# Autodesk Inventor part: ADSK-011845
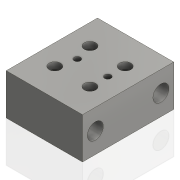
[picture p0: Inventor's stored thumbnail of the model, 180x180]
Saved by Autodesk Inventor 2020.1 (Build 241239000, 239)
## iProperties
Created: 1999-11
Part Number: ADSK-011845
Material: Aluminum
Document SubType Name: Modeling
Designer: sspink
Density: 2.71 g/cm^3
Appearance: Steel
Mass: 161.914 g
Surface Area: 152.118 cm^2
Volume: 59.747 cm^3
Control State: 0
Master: False
Checked Out: False
Shininess: 0.0
Length Units: 11269
Angle Units: 11279
Time Units: 11290
Mass Units: 11283
Length Display Precision: 3
Angle Display Precision: 2
Compacted: True
Dimensions: 47,6x25,6x57 mm
Mass: 0,162 kg
DocNumber: ADSK-011845.ipt
Folder: 01 - Themengebiete\Simplification\01 - Packaging machine\
VDS_Category: 3D Komponenten
Density: 0.0
Volumn: 0.0
Area: 0.0
PropertySet Name: Model Information
Author: sspink
Revision Number: -
Title: Zylinder - Body
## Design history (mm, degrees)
node "Solide1"
  node "Extrusion1" dims "d2" = 56.9976, "d3" = 0
  node "Hole2" dims "d26" = 3.683, "d27" = 9.525, "d28" = 6.35, "d29" = 60 deg, "d30" = 19.05, "d31" = 118 deg
  node "Hole3" dims "d32" = 4.318, "d33" = 7.1374, "d34" = 4.318, "d35" = 60 deg, "d36" = 12.7, "d37" = 118 deg
  node "Extrusion2" dims "d61" = 57.15, "d62" = 0
  node "Hole7" dims "d75" = 3.9624, "d76" = 9.525, "d77" = 6.35, "d78" = 60 deg, "d79" = 12.7, "d80" = 118 deg
sketch "Sketch3"
  geometry: L1 (0, 0)-(0, 56.998) reference; L2 (12.812, 17.499)-(34.812, 17.499); L3 (34.812, 17.499)-(34.812, 39.499); L4 (34.812, 39.499)-(12.812, 39.499); L5 (12.812, 39.499)-(12.812, 17.499); L6 (0, 0)-(47.625, 0) reference; 6 further points
  constraints: 8 end point, 4 midpoint, 2 coincident, 2 parallel, 1 horizontal, 1 horizontal alignment, 1 perpendicular, 1 vertical alignment
  dimensions: "d81" = 22 distance of L4.end L2.start; "d82" = 22 distance of L3.end L4.end
node "Corps solides"
node "Corps surfaciques"
sketch "Sketch1"
  geometry: L1 (-19.199, -4.517)-(28.426, -4.517) reference; L2 (28.426, -4.517)-(28.426, 21.086) reference; L3 (28.426, 21.086)-(-19.199, 21.086); L4 (-19.199, 21.086)-(-19.199, -4.517)
  constraints: 8 end point, 2 horizontal, 2 parallel, 1 perpendicular, 1 vertical
  dimensions: "d0" = 47.625 distance of L1.start L1.end; "d1" = 25.6032 distance of L1.end L2.end
sketch "Sketch4"
  geometry: C1 r 1.841 at (12.813, -17.499) reference; C2 r 1.841 at (34.812, -17.499) reference; C3 r 1.841 at (34.812, -39.499) reference; C4 r 1.841 at (12.813, -39.499) reference; 4 further points
  constraints: 4 coincident
sketch "Sketch7"
  geometry: L1 (56.998, 0)-(56.998, 25.603) reference; L2 (0, 25.603)-(56.998, 25.603) reference; L3 (0, 25.603)-(0, 0) reference; L4 (0, 0)-(56.998, 0) reference; L5 (28.499, 25.603)-(28.499, 0); L6 (0, 12.802)-(56.998, 12.802); C1 r 5.004 at (48.997, 12.802); C2 r 5.004 at (8.001, 12.802)
  constraints: 4 end point, 4 midpoint, 2 centre point, 2 point on line, 1 equal radius
  dimensions: "d58" = 20.4978 distance from line of L5 C2.centre (= d59); "d59" = 20.4978 distance from line of L5 C1.centre; "d60" = 10.0076 diameter of C2
sketch "Sketch9"
  geometry: L1 (47.625, 0)-(47.625, -56.998) reference; L2 (0, 0)-(0, -56.998) reference; L3 (0, -28.499)-(47.625, -28.499); 2 further points
  constraints: 2 end point, 2 midpoint, 2 point on line
  dimensions: "d73" = 15.875 distance from line of point (15.875, -28.499) L2; "d74" = 12.7 distance from line of L1 point (34.925, -28.499)
